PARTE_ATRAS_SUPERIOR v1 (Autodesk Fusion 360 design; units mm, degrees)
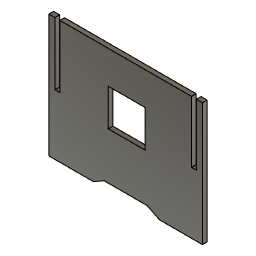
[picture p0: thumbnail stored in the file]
parameter "d10" = 15
parameter "d11" = 0
sketch "Sketch1" plane through (0, 0, 0) normal (0, 1, 0) x axis (1, 0, 0)
  line L1 (500, 0) -> (500, -400)
  line L2 (0, -400) -> (0, 0)
  line L3 (20, -400) -> (0, -400)
  line L4 (20, -200) -> (20, -400)
  line L5 (0, -400) -> (0, -200)
  line L6 (480, -400) -> (500, -400)
  line L7 (480, -200) -> (480, -400)
  line L8 (500, -400) -> (500, -200)
  line L9 (35.75, -196.5937) -> (35.75, -400)
  line L10 (20, -196.5937) -> (35.75, -196.5937)
  line L11 (20, -400) -> (20, -196.5937)
  line L12 (464.25, -200) -> (464.25, -400)
  line L13 (480, -200) -> (464.25, -200)
  line L14 (480, -400) -> (480, -200)
  line L15 (20, -400) -> (0, -400)
  line L16 (464.25, -400) -> (35.75, -400)
  line L17 (500, -400) -> (480, -400)
  line L18 (179.7297, -19.8456) -> (249.7297, -19.9214)
  line L19 (319.7297, -19.9631) -> (249.7297, -19.9214)
  line L20 (360.0001, 0) -> (359.7297, 0)
  line L21 (359.7297, 0) -> (319.7297, -19.9631)
  line L22 (145, 0) -> (179.7297, -19.8456)
  line L23 (359.7297, 0) -> (500, 0)
  line L24 (0, 0) -> (145, 0)
  line L25 (179.7297, -19.8456) -> (319.7297, -19.9631)
  line L26 (-25.0096, -19.6736) -> (0, -19.6946)
  line L27 (316.8201, -302.3203) -> (196.8201, -302.3203)
  line L28 (316.8201, -182.3203) -> (316.8201, -302.3203)
  line L29 (196.8201, -182.3203) -> (316.8201, -182.3203)
  line L30 (196.8201, -302.3203) -> (196.8201, -182.3203)
  point P24 (359.7297, 0)
  point P25 (145, 0)
  point P26 (0, -19.6946)
  point P2 (0, -400)
  point P3 (500, -400)
  point P5 (0, 0)
  point P6 (20, -400)
  point P8 (0, -200)
  point P9 (480, -400)
  point P11 (500, -200)
  point P12 (35.75, -400)
  point P15 (464.25, -400)
  point P19 (249.7297, -19.9214)
  point P20 (179.7297, -19.8456)
  point P21 (319.7297, -19.9631)
  point P23 (145, 0)
  point P27 (196.8201, -302.3203)
  point P28 (316.8201, -302.3203)
  point P30 (196.8201, -182.3203)
  horizontal L15
  vertical L1
  horizontal L23
  vertical L2
  horizontal L3
  vertical L4
  vertical L5
  horizontal L6
  vertical L7
  vertical L8
  vertical L9
  horizontal L10
  vertical L11
  vertical L12
  horizontal L13
  vertical L14
  collinear L15 L16
  collinear L16 L17
  perpendicular L7 L20
  coincident L21 P24
  coincident L22 P25
  collinear L23 L24
  coincident L2 P26
  collinear L25 L26
  horizontal L27
  vertical L28
  horizontal L29
  vertical L30
  dimension "d1" distance P2 P3 = 500
  dimension "d2" distance P2 P5 = 400
  dimension "d3" distance P2 P6 = 20
  dimension "d4" distance P2 P8 = 200
  dimension "d5" distance P3 P9 = 20
  dimension "d6" distance P3 P11 = 200
  dimension "d7" distance P6 P12 = 15.75
  dimension "d8" distance P9 P15 = 15.75
  dimension "d18" distance P19 P20 = 70
  dimension "d19" distance P19 P21 = 70
  dimension "d26" distance P20 P23 = 40
  dimension "d27" distance P21 P24 = 40
  dimension "d36" distance P27 P28 = 120
  dimension "d37" distance P27 P30 = 120
extrude "Extrude3" new body sketch "Sketch1" profile of L17 L1 L24 L2 L3 L4 L5 L6 L7 L8 L9 L10 L11 L12 L13 L14 L18 L19 L20 L21 L22 along normal blind 15
sketch "Sketch4" plane through (0, 0, 0) normal (0, -1, 0) x axis (1, 0, 0)
  line L1 (249.7297, 19.9214) -> (179.7297, 19.8456)
  line L2 (319.7297, 19.9631) -> (249.7297, 19.9214)
  line L3 (359.7297, 0) -> (319.7297, 19.9631)
  line L4 (500, 0) -> (359.7297, 0)
  line L5 (500, 400) -> (500, 0)
  line L6 (480, 400) -> (500, 400)
  line L7 (480, 200) -> (480, 400)
  line L8 (464.25, 200) -> (480, 200)
  line L9 (464.25, 400) -> (464.25, 200)
  line L10 (35.75, 400) -> (464.25, 400)
  line L11 (35.75, 196.5937) -> (35.75, 400)
  line L12 (20, 196.5937) -> (35.75, 196.5937)
  line L13 (20, 400) -> (20, 196.5937)
  line L14 (0, 400) -> (20, 400)
  line L15 (0, 0) -> (0, 400)
  line L16 (145, 0) -> (0, 0)
  line L17 (179.7297, 19.8456) -> (145, 0)
  line L18 (313.3836, 293.0026) -> (193.3836, 293.0026)
  line L19 (313.3836, 173.0026) -> (313.3836, 293.0026)
  line L20 (193.3836, 173.0026) -> (313.3836, 173.0026)
  line L21 (193.3836, 293.0026) -> (193.3836, 173.0026)
  point P19 (193.3836, 293.0026)
  point P20 (313.3836, 293.0026)
  point P22 (193.3836, 173.0026)
  horizontal L18
  vertical L19
  horizontal L20
  vertical L21
  dimension "d38" distance P19 P20 = 120
  dimension "d39" distance P19 P22 = 120
extrude "Extrude4" cut sketch "Sketch4" profile of L18 L19 L20 L21 against normal blind 220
